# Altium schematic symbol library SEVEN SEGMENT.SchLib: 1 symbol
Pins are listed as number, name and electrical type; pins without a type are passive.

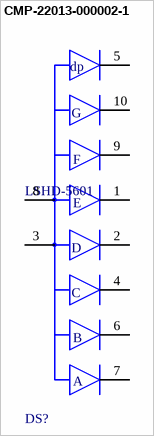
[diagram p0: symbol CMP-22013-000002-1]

## CMP-22013-000002-1
designator DS?, comment LSHD-5601
LED 7-SEG .56" GREEN 565NM CA; Manufacturer: Lite-On; Wavelength: 569nm; Luminous Intensity: 2.4mcd; Forward Current: 20mA; Forward Voltage: 2.1V; Element Config: Common Anode; Reverse Voltage: 5V
footprint FP-LSHD-5601-MFG
pins: 1 CATHODE E, 2 CATHODE D, 3 COMMON ANODE, 4 CATHODE C, 5 CATHODE DP, 6 CATHODE B, 7 CATHODE A, 8 COMMON ANODE, 9 CATHODE F, 10 CATHODE G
